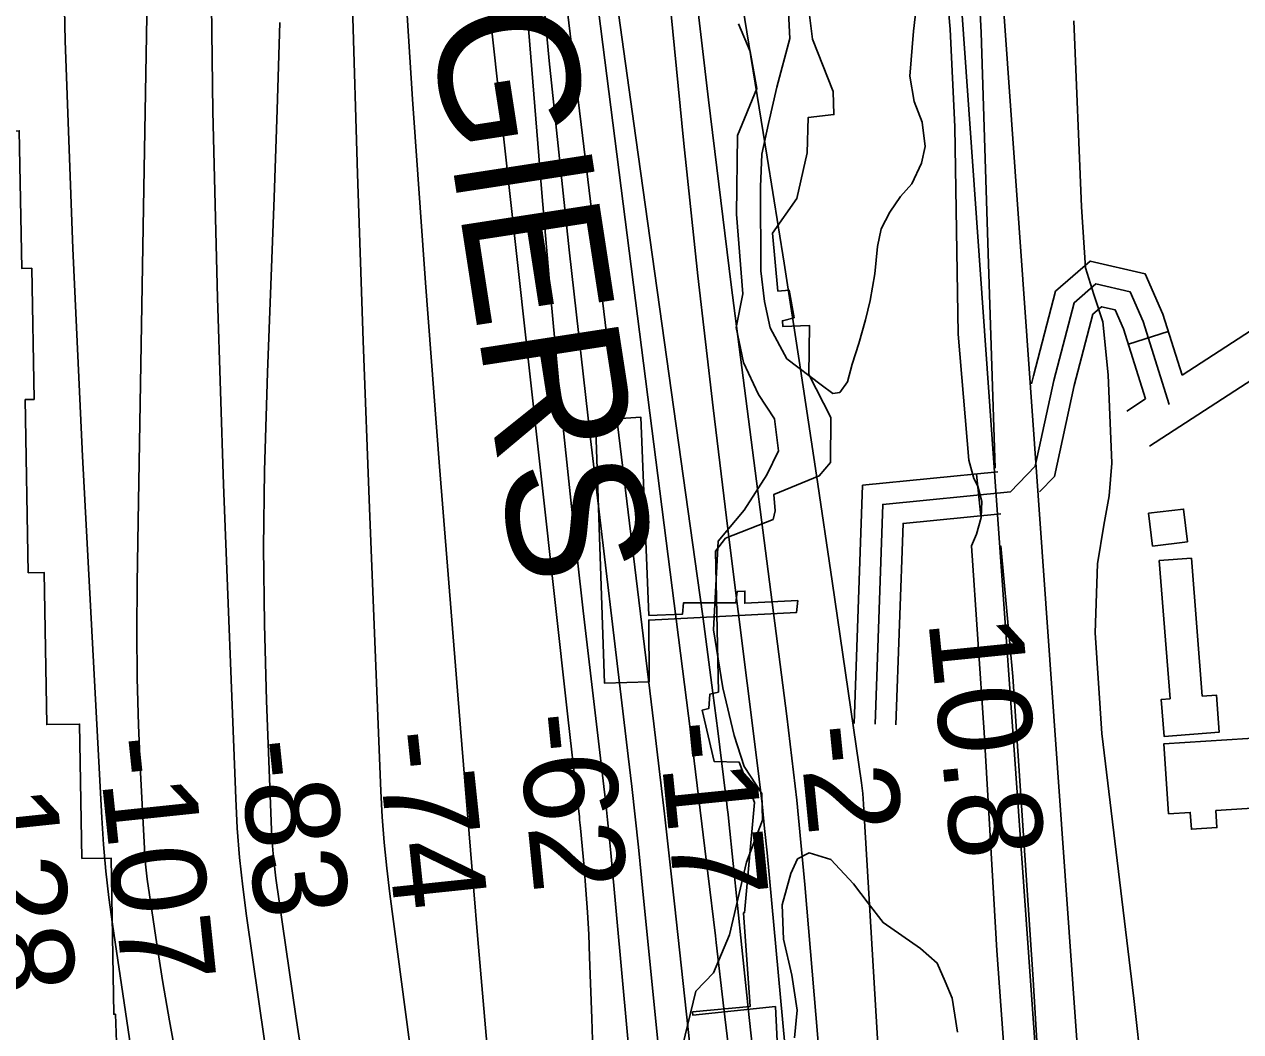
# Model space of a CAD drawing. Extents: x 3677843 to 3715951, y 511991 to 537744.
# Drawn here: x 3684961 to 3685832, y 528590 to 529311 of the extents above; entities that cross this region are included whole.
import ezdxf

# ---------------------------------------------------------------- set-up
doc = ezdxf.new("R2010")
doc.units = 0
for name, color, linetype in [('V-BLDG-OTLN', 7, 'Continuous'), ('V-CHAN-DOCK', 7, 'Continuous'), ('V-FLOD-BASE', 7, 'Continuous'), ('V-LEVE-TOET', 7, 'Continuous'), ('V-RIVR-EDGE', 7, 'Continuous'), ('V-RIVR-RANG', 7, 'Continuous'), ('V-ROAD-CNTR', 7, 'Continuous'), ('V-RRAP-RVMT', 7, 'Continuous'), ('V-RRAP-RVMT-IDEN', 7, 'Continuous'), ('V-SITE-VEGE', 7, 'Continuous'), ('V-SURV-LINE', 7, 'Continuous'), ('V-TOPO-DPTH', 7, 'Continuous'), ('V-TOPO-MAJR', 7, 'Continuous'), ('V-TOPO-MINR', 7, 'Continuous'), ('V-TOPO-WATR', 7, 'Continuous'), ('V-UTIL-IDEN', 7, 'Continuous')]:
    doc.layers.add(name, color=color, linetype=linetype)

msp = doc.modelspace()

# ---------------------------------------------------------------- linework, layer by layer
at = {"layer": 'V-BLDG-OTLN'}
for points in [[(3685793.9, 528940.48), (3685768.85, 528937.52), (3685766.06, 528961.09), (3685791.12, 528964.05)], [(3685796.72, 528928.98), (3685804.48, 528830.08), (3685814.53, 528830.87), (3685816.61, 528804.37), (3685777.11, 528801.27), (3685775.04, 528827.73), (3685781.37, 528828.23), (3685773.66, 528927.17)], [(3685780.23, 528745.78), (3685777.02, 528795.91), (3685852.07, 528800.71), (3685855.27, 528750.78), (3685814.17, 528748.15), (3685814.96, 528735.92), (3685796.63, 528734.75), (3685795.86, 528746.78)]]:
    msp.add_lwpolyline(points, close=True, dxfattribs=at)
at = {"layer": 'V-CHAN-DOCK'}
msp.add_lwpolyline([(3685514.93, 528898.5), (3685476.85, 528896.61), (3685476.89, 528905.36), (3685471.48, 528905.13), (3685470.42, 528896.9), (3685432.85, 528896.82), (3685432.3, 528888.84), (3685408.11, 528887.92), (3685402.33, 529029.97), (3685369.9, 529027.8), (3685376.25, 528839.44), (3685408.41, 528840.33), (3685408.1, 528884.58), (3685513.87, 528890.02), (3685514.93, 528898.5)], dxfattribs=at)
at = {"layer": 'V-FLOD-BASE'}
for points in [[(3685656.22, 528993.26), (3685651.31, 529139.61), (3685646.21, 529305.39), (3685643.67, 529351.86), (3685637.16, 529448.93), (3685635.69, 529457.24), (3685623.7, 529477.25), (3685562.22, 529589.74)], [(3685778.8, 527118.29), (3685782.27, 527187.71), (3685782.4, 527245.31), (3685778.16, 527322.97), (3685768.12, 527497.03), (3685764.14, 527549.03), (3685756.22, 527648.18), (3685744.41, 527790.3), (3685737.38, 527870.72), (3685730.29, 527955.3), (3685719.35, 528080.77), (3685712.75, 528186.87), (3685702.61, 528299.87), (3685691.75, 528486.41), (3685683.43, 528627.17), (3685668.8, 528844.21), (3685660.24, 528937.79)]]:
    msp.add_lwpolyline(points, dxfattribs=at)
at = {"layer": 'V-LEVE-TOET'}
for points in [[(3685663.81, 528559.22), (3685657.39, 528647.96), (3685648.22, 528803.99), (3685639.27, 528937.82), (3685642.65, 528946.18), (3685646.01, 528958), (3685646.66, 528969.42), (3685643.77, 528980.49), (3685640.95, 528986.02), (3685637.35, 528999.17), (3685629.52, 529089.29), (3685627.36, 529237.75), (3685623.9, 529307.8), (3685616.85, 529388.91)], [(3685712.52, 529313.81), (3685718, 529180.64), (3685720.94, 529136.78), (3685726.76, 529117.64), (3685733.19, 529098.28), (3685737.04, 529060.15), (3685739.74, 528997.04), (3685737.89, 528973.43), (3685733.93, 528952.57), (3685729.35, 528924.78), (3685727.76, 528875.5), (3685732.63, 528803.38), (3685755.32, 528613.49), (3685761.4, 528559.43)]]:
    msp.add_lwpolyline(points, dxfattribs=at)
at = {"layer": 'V-RIVR-EDGE'}
for points in [[(3685489.04, 528760.39), (3685476.48, 528779.63), (3685469.33, 528801.86), (3685461.01, 528836.1), (3685454.51, 528877.54), (3685457.67, 528941.16), (3685476.33, 528963.33), (3685492.61, 528988.5), (3685501.05, 529005.89), (3685498.11, 529028.71), (3685486.75, 529046.15), (3685476, 529068.99), (3685470.66, 529094.21), (3685475.52, 529118.21), (3685470.86, 529175.26), (3685471.6, 529231.69), (3685485.49, 529265.27), (3685480.75, 529291.7), (3685472.39, 529311.53)], [(3685500.61, 527853.86), (3685503.05, 527870.07), (3685502.49, 527888.08), (3685495.31, 527896.5), (3685487.54, 527911.53), (3685478.85, 528038.22), (3685463.51, 528146.92), (3685454.73, 528236.99), (3685434.09, 528388.92), (3685424.28, 528546.83), (3685441.86, 528618.83), (3685454.5, 528632), (3685465.98, 528658.99), (3685478.11, 528711.19), (3685489.59, 528741.17), (3685489.04, 528760.39)]]:
    msp.add_lwpolyline(points, dxfattribs=at)
at = {"layer": 'V-ROAD-CNTR'}
for p, q in [((3685751.51, 529082.22), (3685780.13, 529091.21)), ((3685645.78, 528959.27), (3685642.85, 528989.13))]:
    msp.add_line(p, q, dxfattribs=at)
for points in [[(3685789.96, 529059.95), (3685892.64, 529126.57), (3686024.25, 529225.18)], [(3685766.64, 529009.06), (3685909.82, 529101.96), (3686041.73, 529200.79)], [(3685789.96, 529059.95), (3685776.23, 529103.64), (3685763.58, 529132.48), (3685724.28, 529141.74), (3685699.42, 529120.13), (3685683.53, 529059.54), (3685682.25, 529053.68)], [(3685570.11, 528809.95), (3685575.68, 528967.45), (3685667.16, 528976.44), (3685684.77, 528994.75), (3685698.11, 529056.04), (3685712.76, 529111.84), (3685728.32, 529125.38), (3685752.85, 529119.6), (3685762.16, 529098.36), (3685780.82, 529039.02)], [(3685763.84, 529043.01), (3685748.1, 529093.08), (3685742.12, 529106.72), (3685732.37, 529109.02), (3685726.09, 529103.56), (3685712.7, 529052.54), (3685698.52, 528987.41), (3685688, 528976.47)], [(3685750.31, 529034.23), (3685763.84, 529043.01)], [(3685658.05, 528990.62), (3685561.16, 528981.1), (3685555.12, 528810.48)], [(3685660.25, 528960.69), (3685590.21, 528953.81), (3685585.1, 528809.42)]]:
    msp.add_lwpolyline(points, dxfattribs=at)
at = {"layer": 'V-RRAP-RVMT'}
for points in [[(3684901.91, 529465.45), (3684897.92, 529465.24), (3684904.41, 529341.41), (3684927.54, 529342.6), (3684933.18, 529233.77), (3684957.27, 529235.02), (3684959, 529136.4), (3684966.19, 529136.52), (3684967.83, 529042.54), (3684961.53, 529042.43), (3684963.69, 528918.45), (3684974.96, 528918.63), (3684976.88, 528809.66), (3685000.41, 528810.04), (3685002.12, 528713.83), (3685022.97, 528714.11), (3685024.91, 528602.24), (3685026.27, 528602.27)], [(3685500.47, 529120.07), (3685496.62, 529161.66), (3685514.01, 529186.46), (3685521.56, 529219.22), (3685522.32, 529244.61), (3685540.71, 529246.67), (3685540.02, 529263.15), (3685525.4, 529300.74), (3685523.09, 529317.8)], [(3685500.8, 528568.1), (3685498.74, 528607.69), (3685439.54, 528601.59), (3685439.46, 528603.89), (3685480.73, 528607.82), (3685475.8, 528674.84), (3685476.57, 528674.9), (3685483.79, 528753.93), (3685472.79, 528782.87), (3685454.85, 528783.34), (3685446.19, 528820), (3685451.05, 528821.17), (3685451.84, 528831.56), (3685457.93, 528832.96), (3685455.75, 528934.01), (3685463.1, 528943.32), (3685497.07, 528956.63), (3685498.49, 528962.88), (3685497.63, 528974.59), (3685530.1, 528987.98), (3685538.18, 528997.5), (3685538.34, 529029.7), (3685522.57, 529060.48), (3685523.25, 529095.54), (3685504.03, 529094.94), (3685503.74, 529098.93), (3685512.13, 529101.12), (3685508.51, 529120.87), (3685500.47, 529120.07)], [(3685026.27, 528602.27), (3685030.03, 528495.4), (3684997.14, 528494.24), (3685001.48, 528368.5), (3684997.24, 528368.37), (3685002.15, 528228.45), (3685017.73, 528228.97), (3685021.47, 528120.64), (3685020.12, 528120.6), (3685024.96, 527980.68), (3685042.64, 527981.3), (3685046.36, 527872.46), (3685046.04, 527872.45), (3685050.94, 527732.54)]]:
    msp.add_lwpolyline(points, dxfattribs=at)
at = {"layer": 'V-SITE-VEGE'}
for points in [[(3685600.16, 529329.38), (3685597.59, 529306.27), (3685595.1, 529274.06), (3685598.08, 529255.89), (3685603.82, 529241.26), (3685606.1, 529223.79), (3685603.42, 529211.86), (3685596.56, 529197.1), (3685588.26, 529187.93), (3685580.67, 529176.66), (3685574.49, 529164.7), (3685571.82, 529152.08), (3685569.91, 529132.46), (3685566.6, 529113.54), (3685563.24, 529099.52), (3685558.51, 529082.67), (3685553.76, 529067.93), (3685550.38, 529055.31), (3685544.86, 529047.55), (3685539.97, 529046.81), (3685531.51, 529053.02), (3685506.88, 529071.78), (3685495.04, 529093.79), (3685490.88, 529112.69), (3685488.29, 529134.66), (3685488.17, 529194.76), (3685489.05, 529218.26), (3685493.78, 529240.2), (3685499.67, 529266.37), (3685509.08, 529301), (3685508.01, 529319.89)], [(3685512.33, 528585.42), (3685514.24, 528605.03), (3685510.49, 528630.19), (3685504.64, 528656.02), (3685503.7, 528680.5), (3685509.77, 528702.95), (3685514.57, 528713.49), (3685522.92, 528717.77), (3685538.36, 528713.03), (3685554.63, 528695.7), (3685565.26, 528681.81), (3685575.89, 528667.92), (3685602.67, 528649.29), (3685614.66, 528638.91), (3685620.39, 528625.67), (3685625.41, 528613.83), (3685629.15, 528589.37)]]:
    msp.add_lwpolyline(points, dxfattribs=at)
at = {"layer": 'V-SURV-LINE'}
for points in [[(3685706.6, 528272.05), (3685624.03, 529436.06)], [(3685653.96, 529438.17), (3685736.53, 528274.16)]]:
    msp.add_lwpolyline(points, dxfattribs=at)
at = {"layer": 'V-TOPO-DPTH'}
for points in [[(3685370.04, 530751.72), (3685368.31, 529967.1), (3685368.6, 529943.53), (3685369.33, 529919.97), (3685370.73, 529896.45), (3685372.58, 529872.95), (3685423.97, 529320.77), (3685433.27, 529225.96), (3685443.2, 529131.21), (3685454.07, 529036.57), (3685465.57, 528942), (3685485.06, 528788.04), (3685487.2, 528770.49), (3685489.21, 528752.92), (3685491.05, 528735.34), (3685492.77, 528717.74), (3685516.8, 528458.73), (3685530.92, 528311.67), (3685545.68, 528164.67), (3685561.39, 528017.77), (3685577.73, 527870.94), (3685610.5, 527584.99)], [(3685610.5, 527584.99), (3685577.73, 527870.94), (3685561.39, 528017.77), (3685545.68, 528164.67), (3685530.92, 528311.67), (3685516.8, 528458.73), (3685492.77, 528717.74), (3685491.05, 528735.34), (3685489.21, 528752.92), (3685487.2, 528770.49), (3685485.06, 528788.04), (3685465.57, 528942), (3685454.07, 529036.57), (3685443.2, 529131.21), (3685433.27, 529225.96), (3685423.97, 529320.77), (3685372.58, 529872.95), (3685370.73, 529896.45), (3685369.33, 529919.97), (3685368.6, 529943.53), (3685368.31, 529967.1), (3685370.04, 530751.72)], [(3685279.52, 530462.8), (3685282.88, 529942.41), (3685283.12, 529928.65), (3685283.57, 529914.89), (3685284.33, 529901.15), (3685285.29, 529887.42), (3685312.21, 529556.49), (3685324.01, 529420.76), (3685336.81, 529285.12), (3685351.1, 529149.63), (3685366.4, 529014.25), (3685393.32, 528787.19), (3685395.84, 528765.4), (3685398.28, 528743.6), (3685400.6, 528721.79), (3685402.84, 528699.97), (3685461.94, 528106.84), (3685471.06, 528014.87), (3685480.13, 527922.88), (3685489.11, 527830.89)], [(3685279.52, 530462.8), (3685282.88, 529942.41), (3685283.12, 529928.65), (3685283.57, 529914.89), (3685284.33, 529901.15), (3685285.29, 529887.42), (3685312.21, 529556.49), (3685324.01, 529420.76), (3685336.81, 529285.12), (3685351.1, 529149.63), (3685366.4, 529014.25), (3685393.32, 528787.19), (3685395.84, 528765.4), (3685398.28, 528743.6), (3685400.6, 528721.79), (3685402.84, 528699.97), (3685461.94, 528106.84), (3685471.06, 528014.87), (3685480.13, 527922.88), (3685489.11, 527830.89)], [(3685526.57, 527788.87), (3685516.52, 527865.92), (3685507.22, 527943.07), (3685498.43, 528020.28), (3685426.45, 528681.23), (3685422.88, 528713.5), (3685419.23, 528745.75), (3685415.47, 528777.99), (3685411.62, 528810.22), (3685348.97, 529328.07), (3685337.72, 529425.77), (3685327.23, 529523.55), (3685317.88, 529621.45), (3685309.29, 529719.42), (3685294.66, 529898.19), (3685294.05, 529906.84), (3685293.57, 529915.49), (3685293.3, 529924.15), (3685293.15, 529932.81), (3685291.97, 530152)], [(3685526.57, 527788.87), (3685516.52, 527865.92), (3685507.22, 527943.07), (3685498.43, 528020.28), (3685426.45, 528681.23), (3685422.88, 528713.5), (3685419.23, 528745.75), (3685415.47, 528777.99), (3685411.62, 528810.22), (3685348.97, 529328.07), (3685337.72, 529425.77), (3685327.23, 529523.55), (3685317.88, 529621.45), (3685309.29, 529719.42), (3685294.66, 529898.19), (3685294.05, 529906.84), (3685293.57, 529915.49), (3685293.3, 529924.15), (3685293.15, 529932.81), (3685291.97, 530152)], [(3685397.32, 530116.58), (3685397.61, 529939.36), (3685397.75, 529930.52), (3685398.05, 529921.69), (3685398.6, 529912.87), (3685399.32, 529904.06), (3685411.25, 529778.41), (3685418.77, 529706.87), (3685427.23, 529635.45), (3685437.1, 529564.21), (3685447.92, 529493.09), (3685492.89, 529216), (3685505, 529140.16), (3685516.84, 529064.28), (3685528.29, 528988.34), (3685539.48, 528912.35), (3685560.35, 528767.94), (3685560.85, 528764.13), (3685561.29, 528760.31), (3685561.63, 528756.48), (3685561.91, 528752.65), (3685600.01, 528112.83)], [(3685585.44, 527605.39), (3685479.18, 528464.15), (3685473.36, 528511.51), (3685467.59, 528558.87), (3685461.91, 528606.25), (3685456.29, 528653.63), (3685455.74, 528658.28), (3685450.36, 528703.34), (3685444.9, 528748.38), (3685439.31, 528793.41), (3685433.64, 528838.43), (3685326.71, 529676.95), (3685321.91, 529716.7), (3685317.46, 529756.5), (3685313.55, 529796.35), (3685310, 529836.24), (3685304.01, 529908.96), (3685303.76, 529912.52), (3685303.56, 529916.08), (3685303.45, 529919.65), (3685303.39, 529923.22), (3685303.01, 530010.84), (3685303.17, 530058.22)], [(3685303.17, 530058.22), (3685303.01, 530010.84), (3685303.39, 529923.22), (3685303.45, 529919.65), (3685303.56, 529916.08), (3685303.76, 529912.52), (3685304.01, 529908.96), (3685310, 529836.24), (3685313.55, 529796.35), (3685317.46, 529756.5), (3685321.91, 529716.7), (3685326.71, 529676.95), (3685433.64, 528838.43), (3685439.31, 528793.41), (3685444.9, 528748.38), (3685450.36, 528703.34), (3685455.74, 528658.28), (3685456.29, 528653.63), (3685461.91, 528606.25), (3685467.59, 528558.87), (3685473.36, 528511.51), (3685479.18, 528464.15), (3685585.44, 527605.39)]]:
    msp.add_lwpolyline(points, dxfattribs=at)
at = {"layer": 'V-TOPO-MAJR'}
for points in [[(3685295.45, 527609.97), (3685245.64, 527879.98), (3685220.9, 528018.6), (3685197.23, 528157.4), (3685175.18, 528296.46), (3685154.21, 528435.7), (3685119.92, 528672.66), (3685117.23, 528693.58), (3685114.98, 528714.55), (3685113.38, 528735.57), (3685112.23, 528756.64), (3685103.47, 528981.65), (3685099.1, 529115.27), (3685095.84, 529248.91), (3685094.26, 529382.57), (3685093.79, 529516.26), (3685094.63, 529824.73), (3685094.54, 529864.21), (3685094.17, 529903.69), (3685093.41, 529943.17), (3685092.37, 529982.64), (3685058.63, 531058.15)], [(3685476.5, 527607.82), (3685431.09, 528153.03), (3685422.79, 528251.17), (3685414.32, 528349.28), (3685405.59, 528447.38), (3685396.69, 528545.46), (3685380.84, 528717.76), (3685379.7, 528729.67), (3685378.5, 528741.58), (3685377.2, 528753.47), (3685375.85, 528765.36), (3685361.07, 528891.09), (3685352.69, 528965.89), (3685344.86, 529040.73), (3685337.84, 529115.66), (3685331.37, 529190.64), (3685275.92, 529876.65), (3685274.61, 529895.47), (3685273.57, 529914.3), (3685272.94, 529933.14), (3685272.59, 529952), (3685265.04, 530943.43)]]:
    msp.add_lwpolyline(points, dxfattribs=at)
at = {"layer": 'V-TOPO-MINR'}
for points in [[(3685610.5, 527584.99), (3685577.73, 527870.94), (3685561.39, 528017.77), (3685545.68, 528164.67), (3685530.92, 528311.67), (3685516.8, 528458.73), (3685492.77, 528717.74), (3685491.05, 528735.34), (3685489.21, 528752.92), (3685487.2, 528770.49), (3685485.06, 528788.04), (3685465.57, 528942), (3685454.07, 529036.57), (3685443.2, 529131.21), (3685433.27, 529225.96), (3685423.97, 529320.77), (3685372.58, 529872.95), (3685370.73, 529896.45), (3685369.33, 529919.97), (3685368.6, 529943.53), (3685368.31, 529967.1), (3685370.04, 530751.72)], [(3685237.36, 527534.85), (3685140.08, 527990.04), (3685115.94, 528108.45), (3685093.29, 528227.12), (3685072.88, 528346.2), (3685053.96, 528465.55), (3685023.98, 528666.83), (3685021.44, 528685.77), (3685019.25, 528704.75), (3685017.6, 528723.78), (3685016.3, 528742.85), (3685002.41, 529001.99), (3684995.54, 529150.69), (3684990.12, 529299.44), (3684986.91, 529448.24), (3684985.15, 529597.09), (3684984.12, 529829.35), (3684983.63, 529863.22), (3684982.69, 529897.07), (3684981.07, 529930.89), (3684978.99, 529964.7), (3684943.62, 530459.04), (3684939.27, 530495.78), (3684932.71, 530532.01)], [(3685335.15, 527848.11), (3685315.34, 527994.24), (3685295.62, 528140.39), (3685276.04, 528286.55), (3685256.55, 528432.72), (3685222.56, 528688.55), (3685220.39, 528706.84), (3685218.55, 528725.16), (3685217.22, 528743.53), (3685216.22, 528761.92), (3685208.04, 528964.65), (3685203.53, 529084.45), (3685199.45, 529204.25), (3685196, 529324.08), (3685192.98, 529443.92), (3685183.25, 529875.71), (3685182.92, 529892.31), (3685182.66, 529908.91), (3685182.5, 529925.51), (3685182.4, 529942.11), (3685180.87, 530468.37)], [(3685489.11, 527830.89), (3685480.13, 527922.88), (3685471.06, 528014.87), (3685461.94, 528106.84), (3685402.84, 528699.97), (3685400.6, 528721.79), (3685398.28, 528743.6), (3685395.84, 528765.4), (3685393.32, 528787.19), (3685366.4, 529014.25), (3685351.1, 529149.63), (3685336.81, 529285.12), (3685324.01, 529420.76), (3685312.21, 529556.49), (3685285.29, 529887.42), (3685284.33, 529901.15), (3685283.57, 529914.89), (3685283.12, 529928.65), (3685282.88, 529942.41), (3685279.52, 530462.8)], [(3685598.67, 527790.1), (3685590.93, 527865.97), (3685583.8, 527941.9), (3685577.06, 528017.88), (3685519.75, 528695.11), (3685517, 528725.3), (3685513.98, 528755.46), (3685510.57, 528785.58), (3685506.9, 528815.67), (3685467.12, 529124.64), (3685450.75, 529257.07), (3685435.29, 529389.61), (3685421.19, 529522.29), (3685407.98, 529655.08), (3685385.97, 529888.51), (3685384.68, 529904.67), (3685383.69, 529920.83), (3685383.16, 529937.02), (3685382.94, 529953.23), (3685383.08, 530343.35)], [(3685526.57, 527788.87), (3685516.52, 527865.92), (3685507.22, 527943.07), (3685498.43, 528020.28), (3685426.45, 528681.23), (3685422.88, 528713.5), (3685419.23, 528745.75), (3685415.47, 528777.99), (3685411.62, 528810.22), (3685348.97, 529328.07), (3685337.72, 529425.77), (3685327.23, 529523.55), (3685317.88, 529621.45), (3685309.29, 529719.42), (3685294.66, 529898.19), (3685294.05, 529906.84), (3685293.57, 529915.49), (3685293.3, 529924.15), (3685293.15, 529932.81), (3685291.97, 530152)], [(3685395.11, 527584.05), (3685330.31, 528183.12), (3685320.74, 528274.4), (3685311.59, 528365.72), (3685303.05, 528457.09), (3685294.92, 528548.51), (3685285.76, 528655.73), (3685282.55, 528693.57), (3685279.38, 528731.41), (3685276.28, 528769.26), (3685273.21, 528807.11), (3685258.17, 528994.53), (3685248.14, 529126.13), (3685238.82, 529257.77), (3685230.55, 529389.49), (3685222.99, 529521.25), (3685202.96, 529896.67), (3685202.65, 529903.37), (3685202.39, 529910.08), (3685202.23, 529916.79), (3685202.13, 529923.5), (3685200.59, 530095.68)], [(3685368.45, 528560.97), (3685367.19, 528599.13), (3685365.71, 528643.25), (3685365.03, 528659.33), (3685364.17, 528675.4), (3685363.04, 528691.45), (3685361.72, 528707.49), (3685359.17, 528735.59), (3685358.98, 528737.57), (3685358.78, 528739.55), (3685358.57, 528741.54), (3685358.35, 528743.52), (3685355.87, 528764.8), (3685354.41, 528777.42), (3685352.96, 528790.04), (3685351.54, 528802.67), (3685350.13, 528815.29), (3685237.1, 529834.62), (3685233.19, 529873.15), (3685229.76, 529911.73), (3685227.05, 529950.37), (3685224.82, 529989.04), (3685223.4, 530027.74), (3685222.55, 530066.45)], [(3685585.44, 527605.39), (3685479.18, 528464.15), (3685473.36, 528511.51), (3685467.59, 528558.87), (3685461.91, 528606.25), (3685456.29, 528653.63), (3685455.74, 528658.28), (3685450.36, 528703.34), (3685444.9, 528748.38), (3685439.31, 528793.41), (3685433.64, 528838.43), (3685326.71, 529676.95), (3685321.91, 529716.7), (3685317.46, 529756.5), (3685313.55, 529796.35), (3685310, 529836.24), (3685304.01, 529908.96), (3685303.76, 529912.52), (3685303.56, 529916.08), (3685303.45, 529919.65), (3685303.39, 529923.22), (3685303.01, 530010.84), (3685303.17, 530058.22)], [(3685069.92, 528570.02), (3685064.82, 528597.44), (3685060.17, 528624.93), (3685055.84, 528652.48), (3685048.92, 528698.93), (3685048.33, 528703.3), (3685047.83, 528707.68), (3685047.45, 528712.07), (3685047.15, 528716.47), (3685044.05, 528775.34), (3685042.62, 528809.19), (3685041.66, 528843.05), (3685041.4, 528876.92), (3685041.61, 528910.79), (3685042.35, 528955.41), (3685043.29, 529011.6), (3685044.23, 529067.79), (3685045.2, 529123.99), (3685046.17, 529180.18), (3685050.46, 529427.03)], [(3685485.39, 528549.62), (3685479.95, 528599.79), (3685474.68, 528649.98), (3685465.41, 528740.33), (3685464.87, 528745.35), (3685464.32, 528750.37), (3685463.73, 528755.39), (3685463.12, 528760.41), (3685457.51, 528805.15), (3685454.02, 528832.53), (3685450.44, 528859.9), (3685446.75, 528887.26), (3685442.98, 528914.6), (3685398.77, 529229.85), (3685383.92, 529336.64)], [(3685164.06, 528542.79), (3685155.29, 528600.81), (3685141.06, 528699.77), (3685139.96, 528708.39), (3685139.03, 528717.02), (3685138.38, 528725.68), (3685137.91, 528734.35), (3685134.33, 528826.73), (3685132.85, 528881.61), (3685132.23, 528936.49), (3685132.91, 528991.36), (3685134.45, 529046.24), (3685135.07, 529061.86), (3685137.48, 529124.54), (3685139.77, 529187.23), (3685141.88, 529249.93), (3685143.87, 529312.63)]]:
    msp.add_lwpolyline(points, dxfattribs=at)
at = {"layer": 'V-TOPO-WATR'}
msp.add_lwpolyline([(3685600.01, 528112.83), (3685561.91, 528752.65), (3685561.63, 528756.48), (3685561.29, 528760.31), (3685560.85, 528764.13), (3685560.35, 528767.94), (3685539.48, 528912.35), (3685528.29, 528988.34), (3685516.84, 529064.28), (3685505, 529140.16), (3685492.89, 529216), (3685447.92, 529493.09), (3685437.1, 529564.21), (3685427.23, 529635.45), (3685418.77, 529706.87), (3685411.25, 529778.41), (3685399.32, 529904.06), (3685398.6, 529912.87), (3685398.05, 529921.69), (3685397.75, 529930.52), (3685397.61, 529939.36), (3685397.32, 530116.58)], dxfattribs=at)

# ---------------------------------------------------------------- texts
at = {"layer": 'V-RIVR-RANG'}
for s, rotation, p in [('10.8', 275.70833, (3685608.13, 528884.52)), ('10.8', 275.70833, (3685608.13, 528884.52)), ('-62', 275.70833, (3685313.45, 528816.39)), ('-62', 275.70833, (3685313.45, 528816.39)), ('-17', 275.70833, (3685414.55, 528810.32)), ('-17', 275.70833, (3685414.55, 528810.32)), ('-2', 275.70833, (3685515.29, 528807.92)), ('-2', 275.70833, (3685515.29, 528807.92)), ('-107', 275.99436, (3685013.19, 528799.24)), ('-83', 275.99436, (3685113.94, 528797.37)), ('-74', 275.99436, (3685212.85, 528803.53)), ('-128', 275.99436, (3684913.44, 528791.66))]:
    msp.add_text(s, height=67, rotation=rotation, dxfattribs=at).set_placement(p)
at = {"layer": 'V-RRAP-RVMT-IDEN'}
msp.add_text('ALGIERS', height=100, rotation=278.75274, dxfattribs=at).set_placement((3685225.86, 529479.54))
at = {"layer": 'V-UTIL-IDEN'}
msp.add_text('4-SUB CABLES', height=82.9998, rotation=32.23594, dxfattribs=at).set_placement((3684469.41, 529067.85))

doc.saveas('drawing.dxf')
